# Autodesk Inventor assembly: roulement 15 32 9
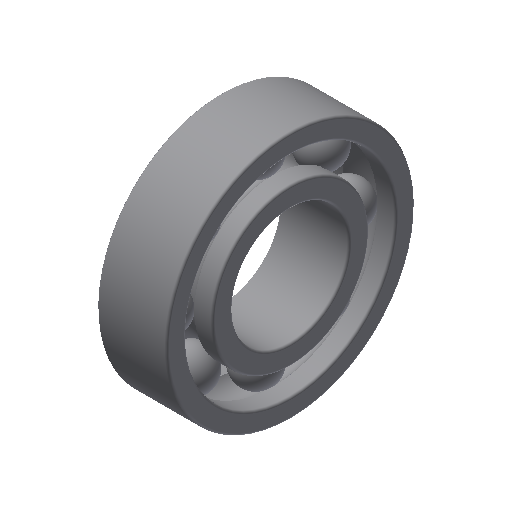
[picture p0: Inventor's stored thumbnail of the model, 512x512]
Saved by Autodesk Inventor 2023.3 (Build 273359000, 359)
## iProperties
Created: 2012-12
Part Number: roulement 15 32 9
Document SubType Name: Assembly
Designer: jost thierry
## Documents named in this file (4)
- E:\Dossier technique\Reducteur\TD02-Reducteur S37\TD02-Reducteur-Ressources\TD02-Reduct-3D\roulement 15 32 9.iam
- E:\Dossier technique\Reducteur\TD02-Reducteur S37\TD02-Reducteur-Ressources\TD02-Reduct-3D\BI 15.32.ipt
- E:\Dossier technique\Reducteur\TD02-Reducteur S37\TD02-Reducteur-Ressources\TD02-Reduct-3D\BILLE 15.32.ipt
- E:\Dossier technique\Reducteur\TD02-Reducteur S37\TD02-Reducteur-Ressources\TD02-Reduct-3D\BE 15.32.ipt
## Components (10 placed, 3 different names)
1. BI 15.32:1
2. BILLE 15.32:2
3. BE 15.32:1
4. BILLE 15.32:3
5. BILLE 15.32:4
6. BILLE 15.32:5
7. BILLE 15.32:6
8. BILLE 15.32:7
9. BILLE 15.32:8
10. BILLE 15.32:9
